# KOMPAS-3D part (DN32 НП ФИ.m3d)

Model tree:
1. Операция без истории:1

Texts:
  DN32 НП ФИ
  133 1 134 1 135 1 136 0 50 1|SPDS|133 1 134 1 135 1 136 0 50 1
  125 1 126 1 127 1 128 0 50 1|SPDS|125 1 126 1 127 1 128 0 50 1
  129 1 130 1 131 1 132 0 50 1|SPDS|129 1 130 1 131 1 132 0 50 1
